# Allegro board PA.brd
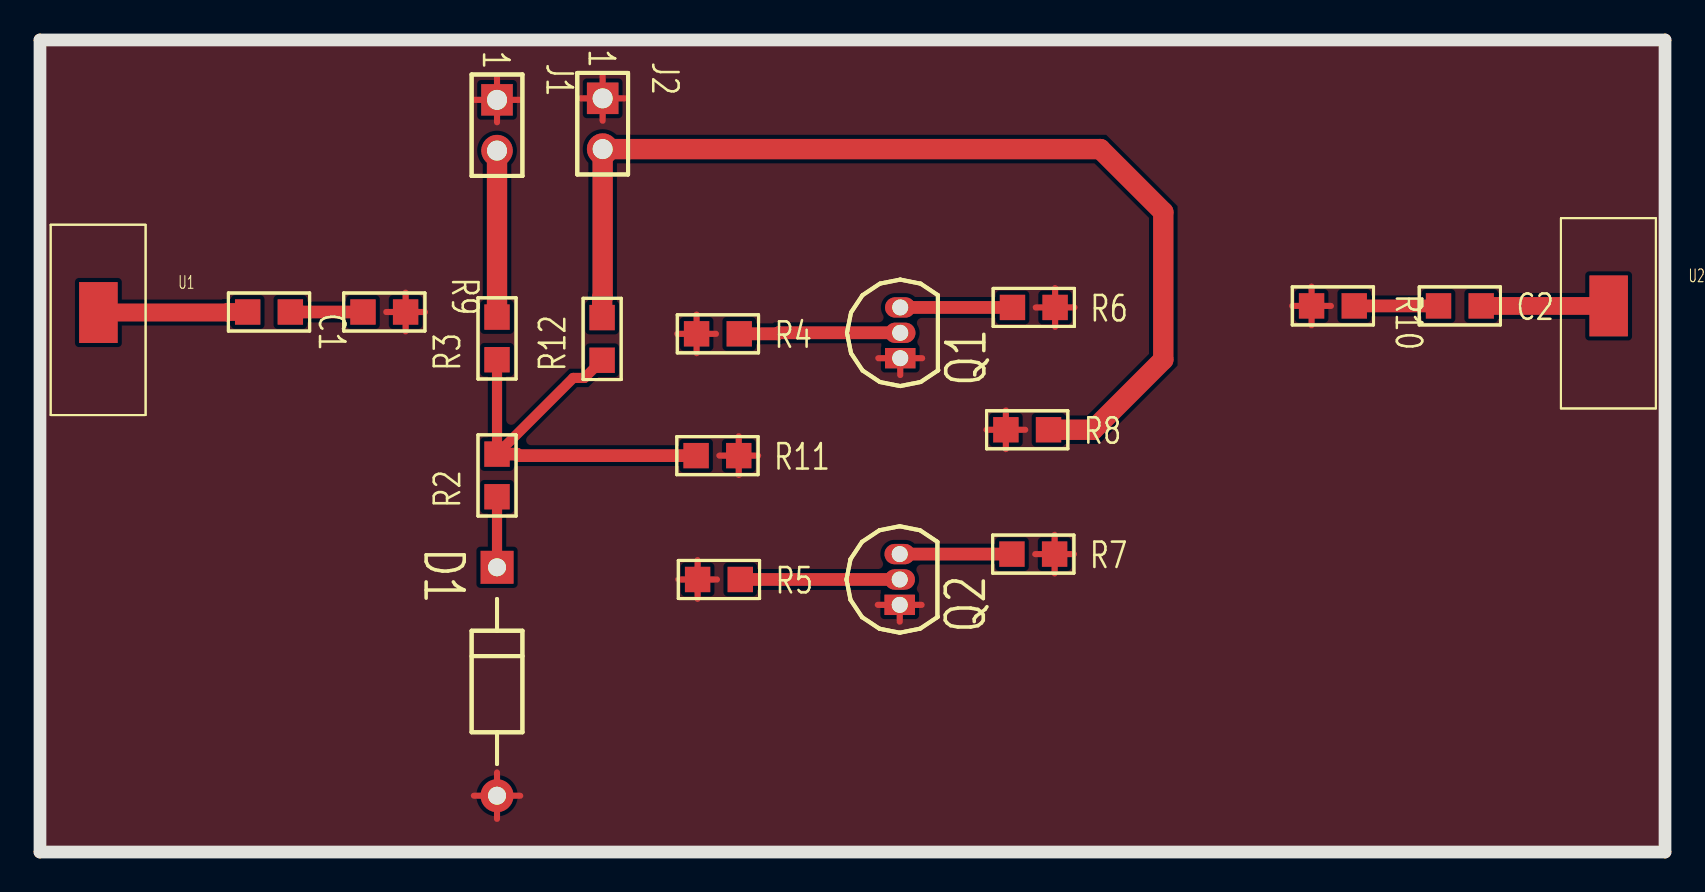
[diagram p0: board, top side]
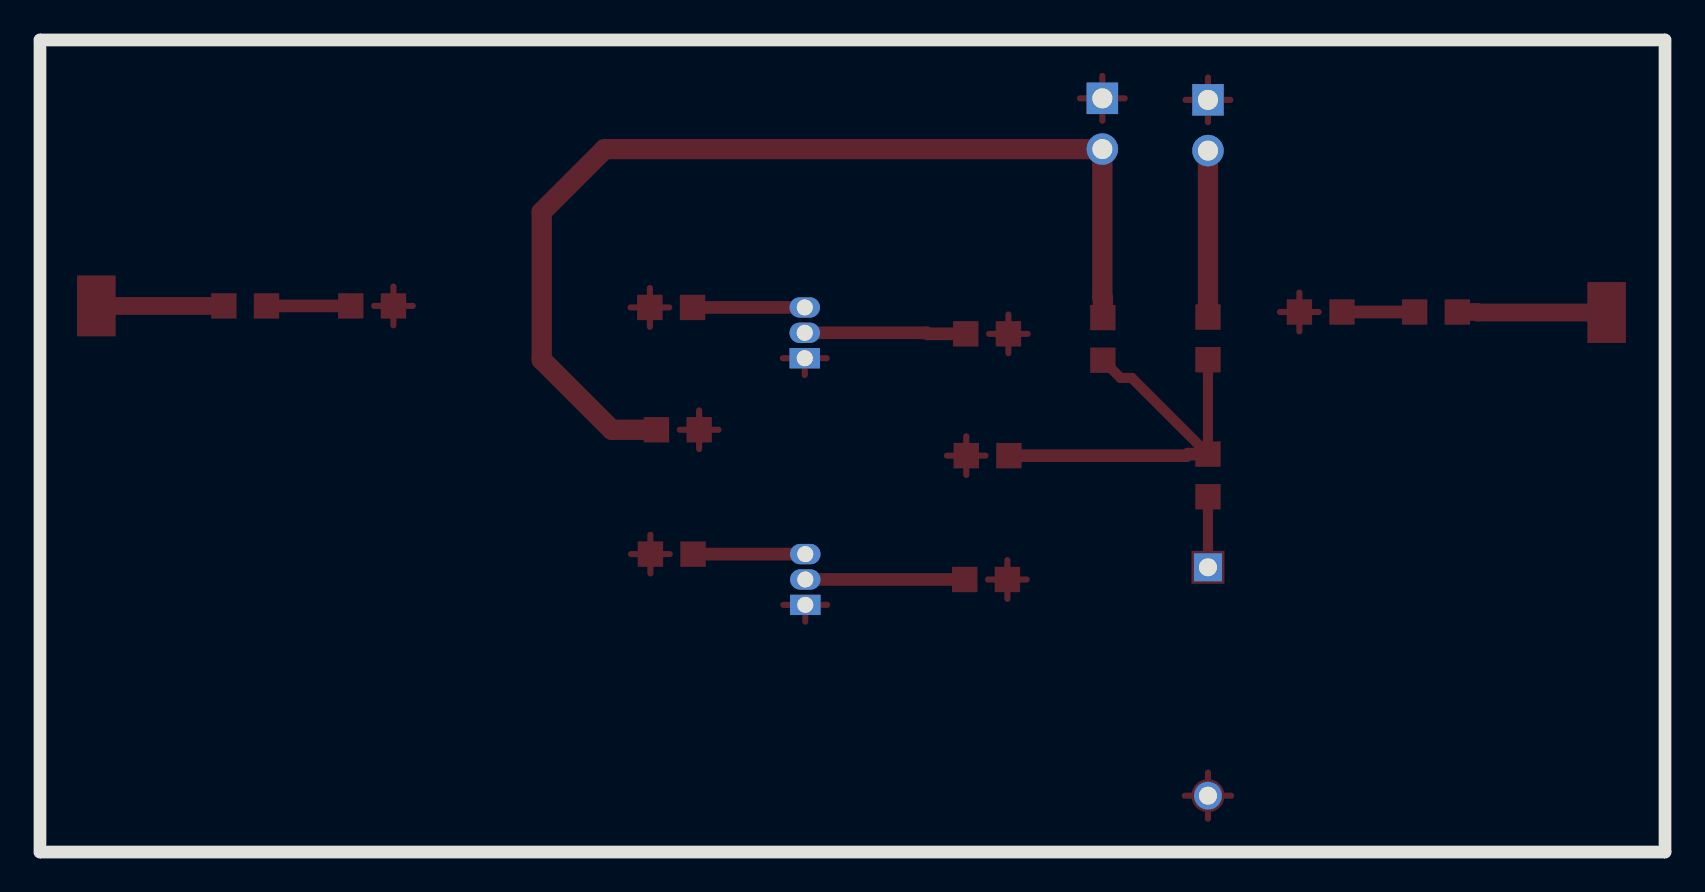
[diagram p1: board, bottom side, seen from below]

Outline 81.28 x 40.64 mm; copper layers: TOP, BOTTOM. Coordinates in mm from the lower left corner of the outline.
Outline path: 0,40.64 0,0 81.28,0 81.28,40.64 0,40.64

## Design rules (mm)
constraint set DEFAULT: min track width 0.305

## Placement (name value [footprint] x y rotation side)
C1  C NP  [SMC0805]  10.39 27.03 0 top
C2  C NP  [SMC0805]  69.95 27.33 0 top
D1  1N4500  [DAX1DO35]  22.86 14.25 270 top
J1  2Pin Header  [BCON_2X1V_100S_1SQ_42D]  22.86 37.64 270 top
J2  2Pin Header  [BCON_2X1V_100S_1SQ_42D]  28.14 37.72 270 top
Q1  Q2N3904  [TO92]  43.03 24.71 90 top
Q2  Q2N3904  [TO92]  43 12.37 90 top
R2  0  [SMR0805]  22.86 17.78 90 top
R3  0  [SMR0805]  22.86 24.64 90 top
R4  R small  [SMC0805]  32.84 25.93 0 top
R5  R small  [SMC0805]  32.89 13.64 0 top
R6  R small  [SMC0805]  48.64 27.25 0 top
R7  R small  [SMC0805]  48.62 14.91 0 top
R8  R small  [SMC0805]  48.31 21.13 0 top
R9  R small  [SMC0805]  16.15 27.03 0 top
R10  R small  [SMC0805]  63.6 27.33 0 top
R11  R small  [SMC0805]  32.82 19.84 0 top
R12  1k  [SMR0805]  28.12 24.61 90 top
U1  SMA_connector  [SMACONNECTOR]  0.53 21.87 0 top
U2  SMA_connector  [SMACONNECTOR]  76.07 22.2 0 top

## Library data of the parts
C1 C2 = C NP
D1 = 1N4500_0
J1 J2 = 2Pin Header
Q1 Q2 = Q2N3904
R2 R3 R12 = R
R4-R11 = R small
U1 U2 = SMA_connector

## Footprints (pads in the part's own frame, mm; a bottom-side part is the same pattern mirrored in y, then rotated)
BCON_2X1V_100S_1SQ_42D
  rect 1.575x1.575 hole 1.001: 1(0,0)
  round 1.575 hole 1.001: 2(2.54,0)
DAX1DO35
  rect 1.651x1.651 hole 0.899: 1(0,0)
  round 1.651 hole 0.899: 2(11.43,0)
SMACONNECTOR
  rect 1.93x3.048 smd: 1(2.388,5.131)
SMC0805
  rect 1.27x1.27 smd: 1(0,0) 2(2.134,0)
SMR0805
  rect 1.27x1.27 smd: 1(0,0) 2(2.134,0)
TO92
  rect 1.016x1.524 hole 0.8: 1(0,0)
  oval 1.016x1.524 hole 0.8: 2(1.27,0) 3(2.54,0)

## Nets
0: D1.2(K) J1.1 J2.1 Q1.1(E) Q2.1(E) R4.1 R5.1 R6.2(B) R7.2(B) R8.1 R9.2(B) R10.1 R11.2(B)
N000400: Q1.2 R4.2(B)
N00470: Q2.3 R7.1
N00477: Q1.3 R6.1
N00731: J2.2 R8.2(B) R12.2(B)
N00881: C2.1 R10.2(B)
N00891: C1.2(B) R9.1
N00987: Q2.2 R5.2(B)
N01135: R2.2(B) R3.1 R11.1 R12.1
N001690: D1.1 R2.1
N002471: J1.2 R3.2(B)
N007750: C1.1 U1.1(VIN)
N007890: C2.2(B) U2.1(VIN)

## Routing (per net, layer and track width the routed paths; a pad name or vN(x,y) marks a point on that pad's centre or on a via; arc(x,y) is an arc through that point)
0: length 50.6
  TOP w0.305: 50.77,26.29 R6.2 ; R6.2 49.81,27.25 ; R6.2 51.74,27.25 ; R6.2 50.77,28.22 ; 27.02,37.72 J2.1 ; J2.1 29.26,37.72 ; J2.1 28.14,36.6 ; J2.1 28.14,38.84 ; 47.34,21.13 R8.1 ; R8.1 48.31,22.1 ; R8.1 49.28,21.13 ; R8.1 48.31,20.17 ; 21.7,2.82 D1.2 ; D1.2 22.86,3.98 ; D1.2 24.02,2.82 ; D1.2 22.86,1.66 ; 43,11.53 Q2.1 ; Q2.1 41.91,12.37 ; Q2.1 44.1,12.37 ; 18.29,26.06 R9.2 ; R9.2 18.29,27.99 ; R9.2 17.32,27.03 ; R9.2 19.26,27.03 ; R5.1 32.89,14.61 ; R5.1 31.93,13.64 ; R5.1 33.86,13.64 ; R5.1 32.89,12.67 ; 21.74,37.64 J1.1 ; J1.1 22.86,38.76 ; J1.1 22.86,36.52 ; J1.1 23.98,37.64 ; R11.2 35.92,19.84 ; R11.2 33.98,19.84 ; R11.2 34.95,20.81 ; R11.2 34.95,18.87 ; R10.1 64.57,27.33 ; R10.1 63.6,28.3 ; R10.1 63.6,26.36 ; R10.1 62.63,27.33 ; R7.2 50.75,15.88 ; R7.2 50.75,13.94 ; R7.2 49.78,14.91 ; R7.2 51.72,14.91 ; 41.93,24.71 Q1.1 ; Q1.1 43.03,23.87 ; Q1.1 44.12,24.71 ; 32.84,24.97 R4.1 ; R4.1 32.84,26.9 ; R4.1 33.81,25.93 ; R4.1 31.87,25.93
N000400: length 8.1
  TOP w0.635: Q1.2 36.93,25.98 36.88,25.93 R4.2
N00470: length 5.6
  TOP w0.635: Q2.3 R7.1
N00477: length 5.6
  TOP w0.635: Q1.3 R6.1
N00731: length 52.4
  TOP w1.016: R8.2 52.68,21.13 56.18,24.64 56.18,32.03 53.04,35.18 J2.2 28.14,27.76 28.12,27.74 R12.2
N00881: length 4.2
  TOP w0.635: R10.2 C2.1
N00891: length 3.6
  TOP w0.635: C1.2 R9.1
N00987: length 8
  TOP w0.635: R5.2 Q2.2
N01135: length 21.9
  TOP w0.508: R3.1 R2.2 26.67,23.73 27.23,23.73 R12.1
  TOP w0.635: R11.1 23.93,19.84 23.85,19.91 R2.2
N001690: length 3.5
  TOP w0.508: R2.1 D1.1
N002471: length 8.3
  TOP w1.016: J1.2 R3.2
N007750: length 7.5
  TOP w0.889: C1.1 9.4,27.03 9.37,27 U1.1
N007890: length 6.4
  TOP w0.889: C2.2 U2.1

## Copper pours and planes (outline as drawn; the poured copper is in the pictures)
0 on TOP: 0.25,40.39 0.25,0.25 81.28,0.25 81.28,40.39

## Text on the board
COMPVAL_TYPE_TOP: FIGURE | SIZE | 31.5 | 35.4 | 39.4 | DRILL CHART: TOP to BOTTOM | ALL UNITS ARE IN MILS | PLATED | QTY | 4 | 2
